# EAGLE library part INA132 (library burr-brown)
Difference Amplifier Low Power, Single-Supply
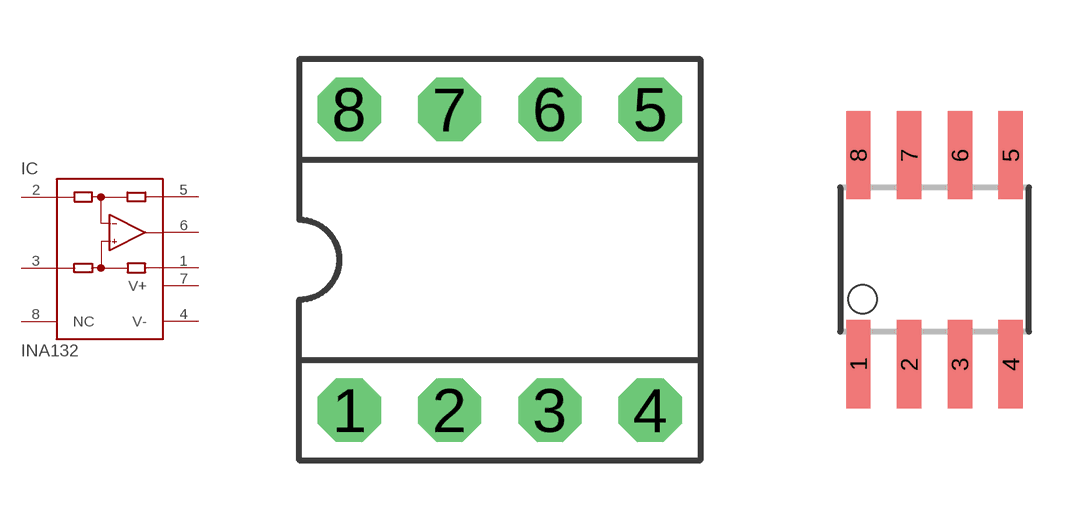
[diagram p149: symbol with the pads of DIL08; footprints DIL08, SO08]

Designator prefix IC

## INA132P (OC_FARNELL: unknown; OC_NEWARK: unknown)  [DIL08]
1  REF  pas
2  -IN  in
3  +IN  in
4  V-  pwr
5  SENSE  pas
6  OUT  out
7  V+  pwr
8  NC  nc

## INA132U (MF: TEXAS INSTRUMENTS; MPN: INA132U; OC_FARNELL: 1212416; OC_NEWARK: 35C1734)  [SO08]
Pads as for DIL08

## Footprint DIL08 (pad centres in mm)
Dual In Line
drill 0.813 pad 1.6 octagon: 1 -3.81,-3.81; 2 -1.27,-3.81; 3 1.27,-3.81; 4 3.81,-3.81; 5 3.81,3.81; 6 1.27,3.81; 7 -1.27,3.81; 8 -3.81,3.81

## Footprint SO08 (pad centres in mm)
Small Outline Package
smd 0.61 x 2.21: 1 -1.905,-2.616; 2 -0.635,-2.616; 3 0.635,-2.616; 4 1.905,-2.616; 5 1.905,2.616; 6 0.635,2.616; 7 -0.635,2.616; 8 -1.905,2.616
